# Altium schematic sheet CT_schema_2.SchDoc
size 388 x 258 mm
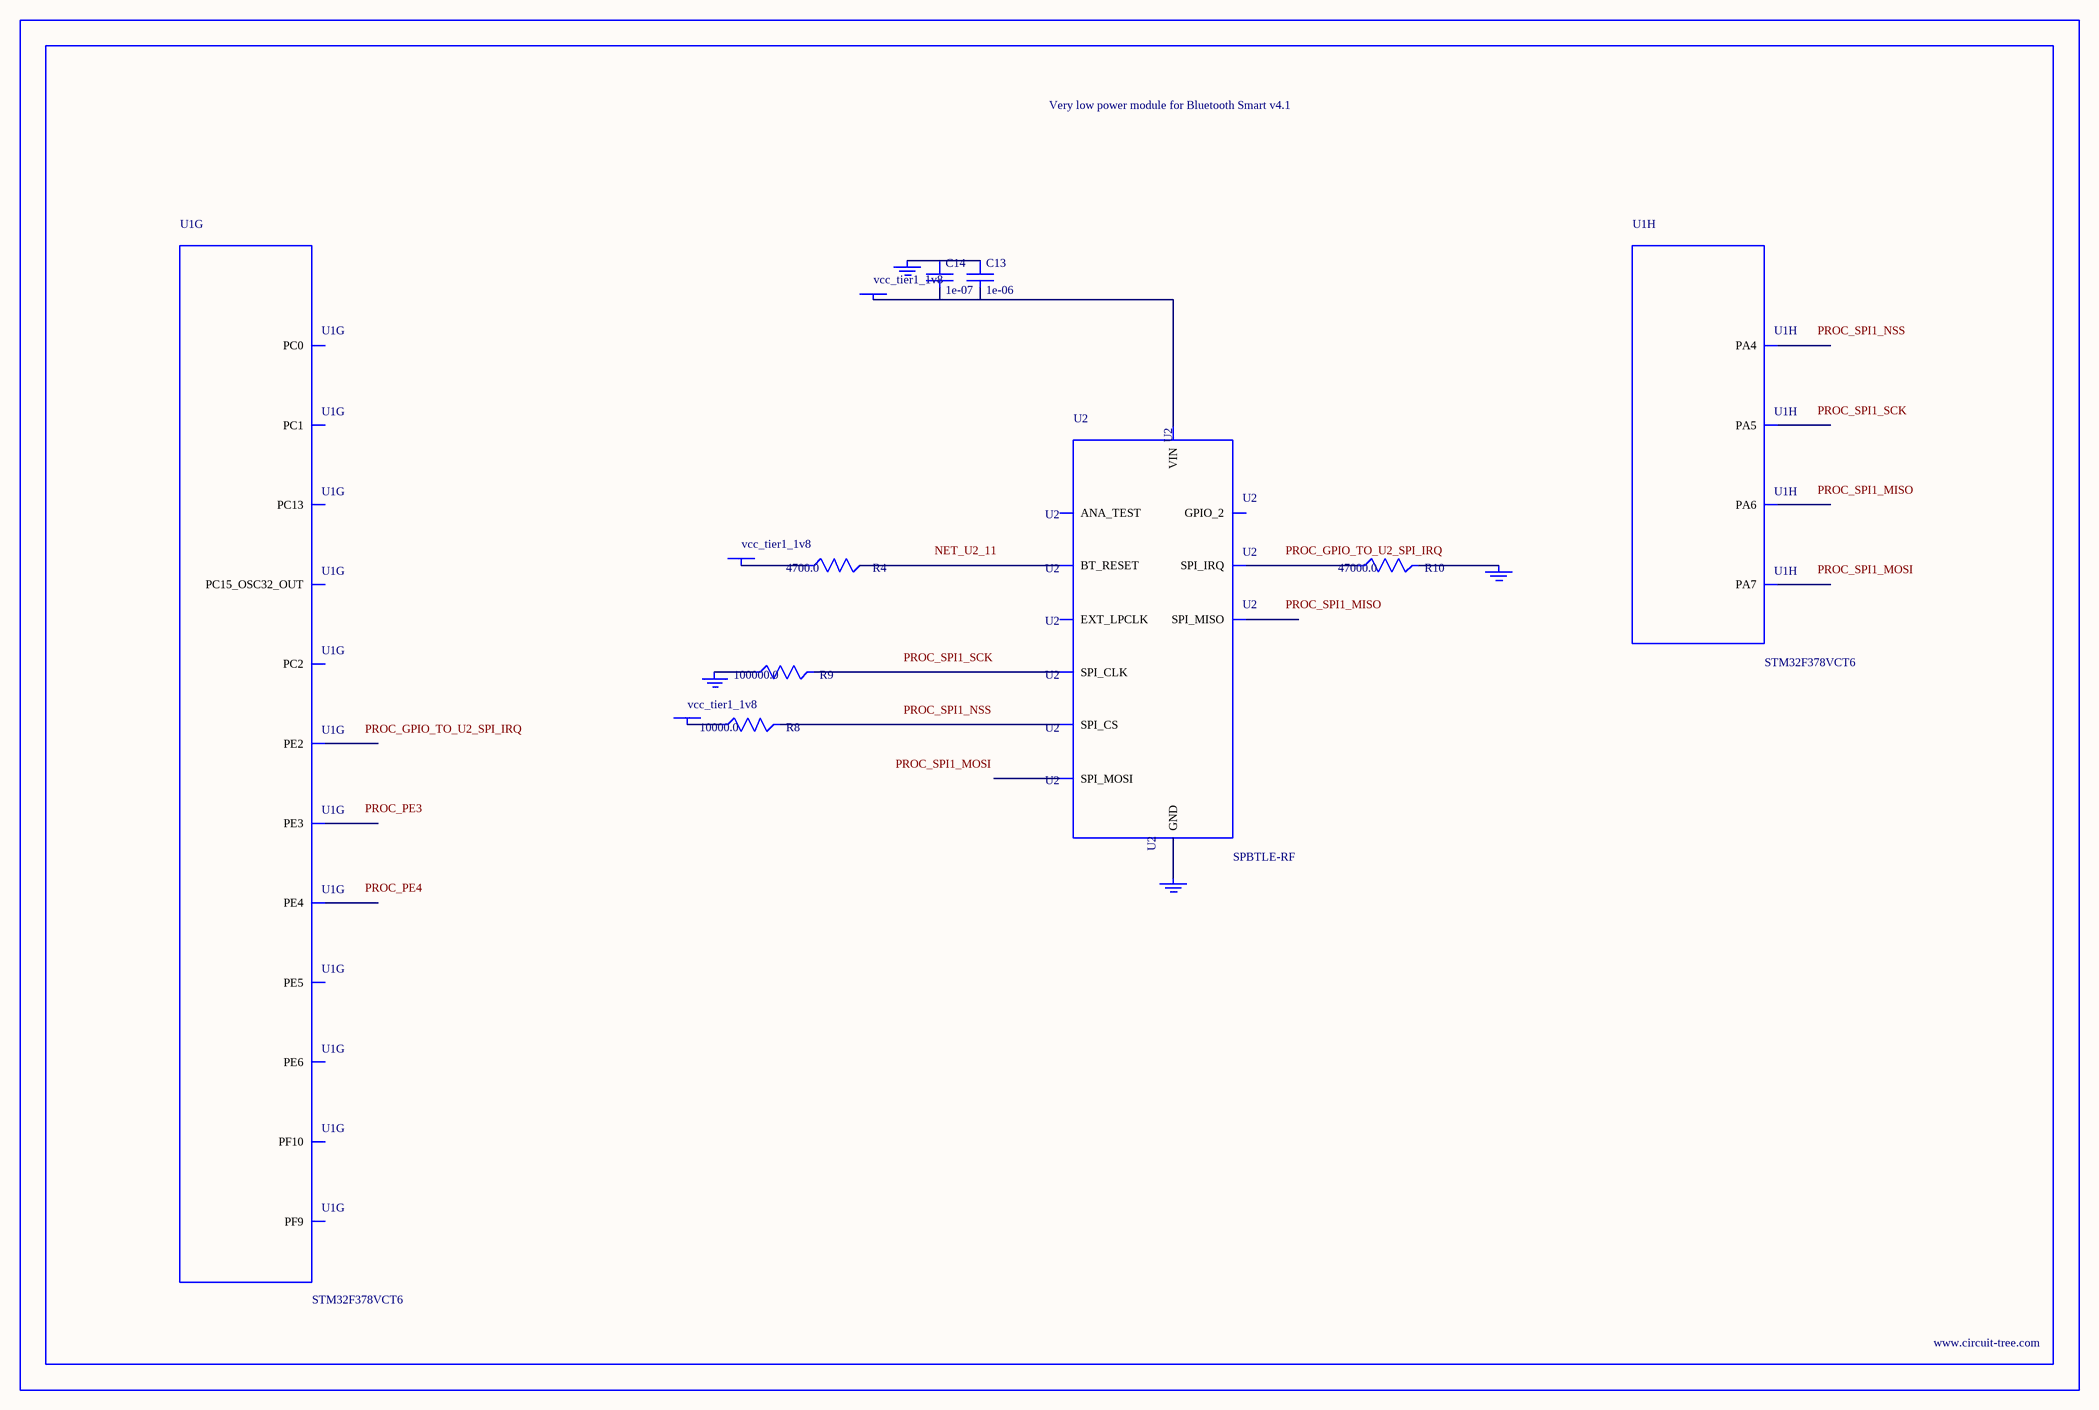
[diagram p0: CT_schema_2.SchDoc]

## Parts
BORDER1  (no value)
C13  1e-06  [C0603]
C14  1e-07  [C0402]
GND_INSTANCE_1_0  (no value)
GND_INSTANCE_1_1  (no value)
GND_INSTANCE_1_2  (no value)
GND_INSTANCE_1_3  (no value)
POWER_INSTANCE_1_0  vcc_tier1_1v8
POWER_INSTANCE_1_1  vcc_tier1_1v8
POWER_INSTANCE_1_2  vcc_tier1_1v8
R4  4700.0  [R0603]
R8  10000.0  [R0603]
R9  100000.0  [R0603]
R10  47000.0  [R0603]
U1  STM32F378VCT6  [LQFP100]  (parts G,H of 8)
U2  SPBTLE-RF  [XCVR_SPBTLE-RF]

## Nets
NetC13_1: C13.1 C14.1 GND_INSTANCE_1_1.0(GND)
NetC13_2: C13.2 C14.2 POWER_INSTANCE_1_0.0(PWR) U2.5(VIN)
NetGND_INSTANCE_1_0_0: GND_INSTANCE_1_0.0(GND) R10.2
NetGND_INSTANCE_1_2_0: GND_INSTANCE_1_2.0(GND) R9.1
NetGND_INSTANCE_1_3_0: GND_INSTANCE_1_3.0(GND) U2.6(GND)
NetPOWER_INSTANCE_1_1_0: POWER_INSTANCE_1_1.0(PWR) R8.1
NetPOWER_INSTANCE_1_2_0: POWER_INSTANCE_1_2.0(PWR) R4.1
NetR4_2: R4.2 U2.11(BT_RESET)
NetR8_2: R8.2 U2.10(SPI_CS)
NetR9_2: R9.2 U2.7(SPI_CLK)
NetR10_1: R10.1 U2.4(SPI_IRQ)

Not connected (* = marked no-connect by the designer): U1 1(PE2) 2(PE3) 3(PE4) 4(PE5) 5(PE6) 7(PC13) 9(PC15_OSC32_OUT) 10(PF9) 11(PF10) 15(PC0) 16(PC1) 17(PC2) 29(PA4) 30(PA5) 31(PA6) 32(PA7); U2 1(EXT_LPCLK) 2(GPIO_2) 3(ANA_TEST) 8(SPI_MISO) 9(SPI_MOSI)

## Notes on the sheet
- Labels drawn without touching a wire or pin: NET_U2_11, PROC_GPIO_TO_U2_SPI_IRQ, PROC_PE3, PROC_PE4, PROC_SPI1_MISO, PROC_SPI1_MOSI, PROC_SPI1_NSS, PROC_SPI1_SCK

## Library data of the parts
BORDER1 = BORDER_PAGE1
C13 = C0603C105K3RACTU
C14 = C0402C104K3RACTU
GND_INSTANCE_1_0-GND_INSTANCE_1_3 = GND
POWER_INSTANCE_1_0-POWER_INSTANCE_1_2 = PWR
R4 = RC0603JR-074K7L
R8 = RC0603JR-0710KL
R9 = RC0603JR-07100KL
R10 = RC0603JR-0747KL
